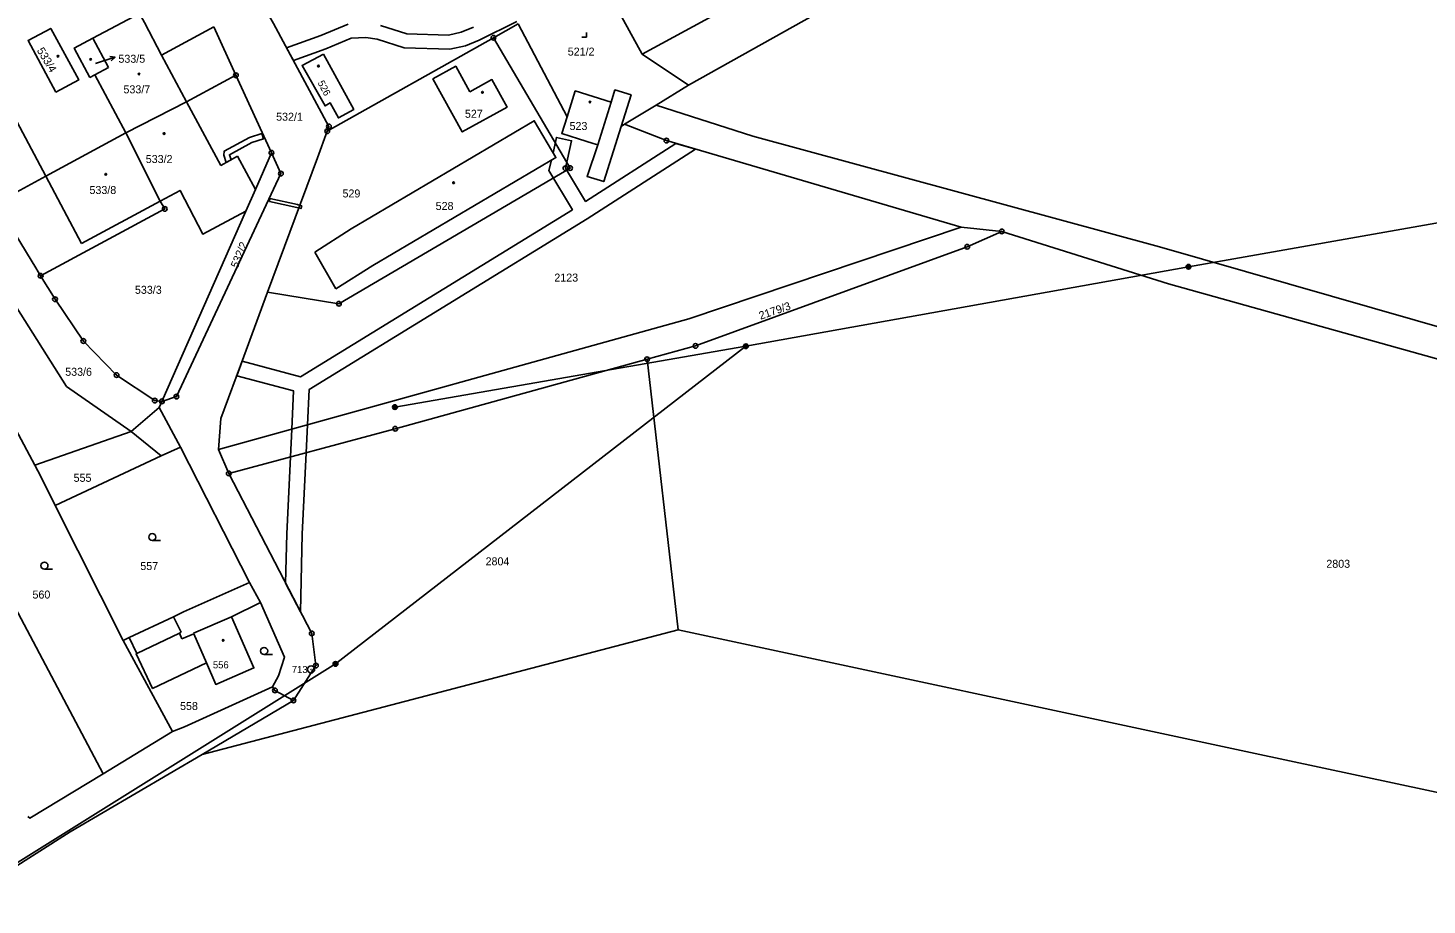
# Model space of a CAD drawing. Extents: x -504988 to -494607, y -1123820 to -1114018.
# Drawn here: x -497467 to -497169.8, y -1121271.7 to -1121085.3 of the extents above; entities that cross this region are included whole.
import ezdxf

# ---------------------------------------------------------------- set-up
doc = ezdxf.new("R2010")
doc.units = 0
for name, color, linetype in [('Hranice parcel', 7, 'Continuous'), ('Parcelní čísla', 7, 'Continuous'), ('Pop  PČ popisy', 7, 'Continuous'), ('Poz předměty', 7, 'Continuous'), ('Vnitřní kresba', 7, 'Continuous'), ('Věcná břemena k části', 7, 'Continuous'), ('Značky bodu BP', 7, 'Continuous'), ('Značky budov', 7, 'Continuous'), ('Značky kultur', 7, 'Continuous')]:
    doc.layers.add(name, color=color, linetype=linetype)

msp = doc.modelspace()

# ---------------------------------------------------------------- linework, layer by layer
at = {"layer": 'Hranice parcel'}
for p, q in [((-497326.68, -1121097.47), (-497278.36, -1121070.36)), ((-497368.15, -1121087.36), (-497362.92, -1121084.41)), ((-497352.5, -1121104.16), (-497362.92, -1121084.41)), ((-497449.93, -1121093.68), (-497453.25, -1121087.45)), ((-497422.86, -1121095.35), (-497427.56, -1121085.06)), ((-497368.15, -1121087.36), (-497403.47, -1121107.24)), ((-497336.51, -1121090.82), (-497326.68, -1121097.47)), ((-497452.84, -1121095.24), (-497449.93, -1121093.68)), ((-497452.84, -1121095.24), (-497453.88, -1121095.8)), ((-497446.25, -1121107.58), (-497452.84, -1121095.24)), ((-497415.33, -1121111.82), (-497422.86, -1121095.35)), ((-497326.68, -1121097.47), (-497333.59, -1121101.69)), ((-497333.59, -1121101.69), (-497340.26, -1121105.75)), ((-497313, -1121108.3), (-497333.59, -1121101.69)), ((-497340.26, -1121105.75), (-497341.01, -1121106.21)), ((-497446.25, -1121107.58), (-497438.94, -1121122.08)), ((-497415.33, -1121111.82), (-497413.31, -1121116.24)), ((-497413.31, -1121116.24), (-497435.51, -1121163.63)), ((-497438.59, -1121164.63), (-497420.76, -1121124.25)), ((-497268.76, -1121127.65), (-497260.14, -1121128.51)), ((-497260.14, -1121128.51), (-497224.71, -1121139.69)), ((-497406.12, -1121132.93), (-497401.6, -1121140.7)), ((-497464.35, -1121137.95), (-497461.3, -1121142.93)), ((-497416.12, -1121141.44), (-497400.97, -1121143.88)), ((-497335.5, -1121155.69), (-497328.91, -1121213.19)), ((-497475.5, -1121159.69), (-497465.57, -1121178.18)), ((-497440.12, -1121164.48), (-497438.59, -1121164.63)), ((-497435.51, -1121163.63), (-497438.59, -1121164.63)), ((-497491.31, -1121167.78), (-497451.07, -1121243.81)), ((-497465.57, -1121178.18), (-497445.11, -1121171.05)), ((-497438.77, -1121176.24), (-497445.11, -1121171.05)), ((-497461.25, -1121186.74), (-497438.77, -1121176.24)), ((-497426.55, -1121174.87), (-497424.38, -1121179.95)), ((-497461.25, -1121186.74), (-497446.83, -1121215.44)), ((-497417.63, -1121207.37), (-497419.94, -1121203.11)), ((-497446.83, -1121215.44), (-497436.32, -1121234.8)), ((-497430.04, -1121239.64), (-497328.91, -1121213.19)), ((-497410.63, -1121228.18), (-497430.04, -1121239.64)), ((-497451.07, -1121243.81), (-497436.32, -1121234.8))]:
    msp.add_line(p, q, dxfattribs=at)
for points in [[(-497301.42, -1121054.09), (-497344.04, -1121077.09), (-497336.51, -1121090.82)], [(-497336.51, -1121090.82), (-497294.14, -1121067.73), (-497301.42, -1121054.09)], [(-497430.47, -1121056.97), (-497414.87, -1121084.34), (-497403.09, -1121106.22), (-497403.47, -1121107.24)], [(-497453.25, -1121087.45), (-497443.38, -1121082.18), (-497442.32, -1121084.16), (-497438.65, -1121091.04), (-497427.56, -1121085.06)], [(-497461.11, -1121098.93), (-497467.03, -1121087.95), (-497462.2, -1121085.37), (-497456.27, -1121096.31), (-497461.11, -1121098.93)], [(-497453.88, -1121095.8), (-497457.2, -1121089.56), (-497453.25, -1121087.45)], [(-497400.97, -1121143.88), (-497351.84, -1121115.06), (-497368.15, -1121087.36)], [(-497404.26, -1121090.86), (-497408.79, -1121093.24), (-497403.93, -1121101.85), (-497402.81, -1121101.23), (-497401.09, -1121104.39), (-497397.82, -1121102.6), (-497404.26, -1121090.86)], [(-497373.16, -1121098.84), (-497376.16, -1121093.42), (-497381.01, -1121096.1), (-497374.75, -1121107.38), (-497365.23, -1121102.09), (-497368.48, -1121096.24), (-497373.16, -1121098.84)], [(-497422.86, -1121095.35), (-497433.33, -1121100.99), (-497446.25, -1121107.58)], [(-497341.01, -1121106.21), (-497338.9, -1121099.52), (-497342.32, -1121098.46), (-497343.12, -1121101.07), (-497350.77, -1121098.65), (-497352.5, -1121104.16)], [(-497401.6, -1121140.7), (-497393.74, -1121135.76), (-497354.86, -1121112.82), (-497359.47, -1121105.01), (-497398.35, -1121127.95), (-497406.12, -1121132.93)], [(-497352.5, -1121104.16), (-497353.63, -1121107.73), (-497350.03, -1121108.85), (-497346.92, -1121109.81), (-497345.99, -1121110.1), (-497348.24, -1121116.84), (-497344.7, -1121117.92), (-497341.01, -1121106.21)], [(-497340.26, -1121105.75), (-497331.39, -1121109.22), (-497268.76, -1121127.65)], [(-497473.48, -1121122.3), (-497463.27, -1121116.77), (-497446.25, -1121107.58)], [(-497403.47, -1121107.24), (-497405.55, -1121112.87), (-497416.12, -1121141.44)], [(-497024.32, -1121160.03), (-497054.02, -1121181.31), (-497226.59, -1121131.82), (-497313, -1121108.3)], [(-497420.76, -1121124.25), (-497418.73, -1121119.61), (-497415.33, -1121111.82)], [(-497438.94, -1121122.08), (-497434.74, -1121119.82), (-497429.9, -1121129.07), (-497420.76, -1121124.25)], [(-497438.94, -1121122.08), (-497437.98, -1121123.74), (-497464.35, -1121137.95)], [(-497464.35, -1121137.95), (-497465.39, -1121136.25), (-497469.57, -1121129.41), (-497471.07, -1121130.21)], [(-497426.55, -1121174.87), (-497326.59, -1121147.07), (-497268.76, -1121127.65)], [(-497260.14, -1121128.51), (-497267.46, -1121131.78), (-497325.19, -1121152.84), (-497335.5, -1121155.69)], [(-497416.12, -1121141.44), (-497421.17, -1121155.08), (-497426.05, -1121168.26), (-497426.55, -1121174.87)], [(-497224.71, -1121139.69), (-497106.85, -1121172.59), (-497052.82, -1121187.14)], [(-497445.11, -1121171.05), (-497458.87, -1121161.47), (-497470.26, -1121143.39)], [(-497461.3, -1121142.93), (-497455.28, -1121151.81), (-497448.21, -1121159.05), (-497440.12, -1121164.48)], [(-497335.5, -1121155.69), (-497388.99, -1121170.45), (-497424.38, -1121179.95)], [(-497445.11, -1121171.05), (-497439.17, -1121165.94), (-497438.59, -1121164.63)], [(-497419.94, -1121203.11), (-497434.67, -1121174.36), (-497438.77, -1121176.24)], [(-497465.57, -1121178.18), (-497464.28, -1121180.58), (-497461.25, -1121186.74)], [(-497424.38, -1121179.95), (-497406.76, -1121213.95), (-497405.85, -1121220.79), (-497410.63, -1121228.18)], [(-497419.94, -1121203.11), (-497434.03, -1121209.39), (-497436.14, -1121210.39), (-497445.51, -1121214.83)], [(-497445.51, -1121214.83), (-497443.92, -1121218.19), (-497444.06, -1121218.25), (-497440.58, -1121225.64), (-497429.12, -1121220.19), (-497427.13, -1121224.77), (-497419.05, -1121221.26), (-497423.78, -1121210.39), (-497417.63, -1121207.37)], [(-497415.06, -1121225.27), (-497413.8, -1121222.94), (-497412.57, -1121219.01), (-497417.63, -1121207.37)], [(-497446.83, -1121215.44), (-497446.38, -1121215.24), (-497445.51, -1121214.83)], [(-497328.91, -1121213.19), (-497207.25, -1121239.23), (-497085.58, -1121265.26), (-497027.04, -1121239.69)], [(-497436.32, -1121234.8), (-497433.81, -1121233.81), (-497415.06, -1121225.27)], [(-497410.63, -1121228.18), (-497414.57, -1121226.05), (-497415.06, -1121225.27)], [(-497430.04, -1121239.64), (-497458.1, -1121256.14), (-497610.28, -1121353.06), (-497671.16, -1121391.21)], [(-497467.06, -1121252.84), (-497466.67, -1121253.17), (-497451.07, -1121243.81)]]:
    msp.add_lwpolyline(points, dxfattribs=at)
at = {"layer": 'Pop  PČ popisy'}
for p, q in [((-497452.73, -1121092.81), (-497451.4, -1121092.39)), ((-497451.4, -1121092.39), (-497448.53, -1121091.51)), ((-497448.53, -1121091.51), (-497449.63, -1121091.33)), ((-497448.53, -1121091.51), (-497449.34, -1121092.28))]:
    msp.add_line(p, q, dxfattribs=at)
at = {"layer": 'Poz předměty'}
for p, q in [((-497025.16, -1121101.65), (-497220.45, -1121136.04)), ((-497220.45, -1121136.04), (-497314.49, -1121152.92)), ((-497314.49, -1121152.92), (-497401.7, -1121220.43)), ((-497314.49, -1121152.92), (-497389.09, -1121165.86)), ((-497401.7, -1121220.43), (-497478.06, -1121268.08))]:
    msp.add_line(p, q, dxfattribs=at)
for centre, radius in [((-497220.45, -1121136.04), 0.5), ((-497220.45, -1121136.04), 0.4), ((-497220.45, -1121136.04), 0.3), ((-497220.45, -1121136.04), 0.2), ((-497220.45, -1121136.04), 0.1), ((-497314.49, -1121152.92), 0.5), ((-497314.49, -1121152.92), 0.4), ((-497314.49, -1121152.92), 0.3), ((-497314.49, -1121152.92), 0.2), ((-497314.49, -1121152.92), 0.1), ((-497389.09, -1121165.86), 0.5), ((-497389.09, -1121165.86), 0.4), ((-497389.09, -1121165.86), 0.3), ((-497389.09, -1121165.86), 0.2), ((-497389.09, -1121165.86), 0.1), ((-497401.7, -1121220.43), 0.5), ((-497401.7, -1121220.43), 0.4), ((-497401.7, -1121220.43), 0.3), ((-497401.7, -1121220.43), 0.2), ((-497401.7, -1121220.43), 0.1)]:
    msp.add_circle(centre, radius, dxfattribs=at)
at = {"layer": 'Vnitřní kresba'}
for p, q in [((-497433.33, -1121100.99), (-497438.65, -1121091.04)), ((-497463.27, -1121116.77), (-497473.72, -1121097.12)), ((-497426.09, -1121114.54), (-497433.33, -1121100.99)), ((-497345.99, -1121110.1), (-497343.12, -1121101.07)), ((-497426.09, -1121114.54), (-497422.5, -1121112.52)), ((-497422.5, -1121112.52), (-497418.73, -1121119.61)), ((-497463.27, -1121116.77), (-497459.42, -1121124.02)), ((-497438.94, -1121122.08), (-497455.66, -1121131.08)), ((-497455.66, -1121131.08), (-497459.42, -1121124.02)), ((-497439.17, -1121165.94), (-497434.67, -1121174.36)), ((-497436.14, -1121210.39), (-497434.48, -1121213.69)), ((-497431.85, -1121213.91), (-497423.78, -1121210.39)), ((-497443.92, -1121218.19), (-497434.87, -1121213.86)), ((-497434.48, -1121213.69), (-497434.87, -1121213.86)), ((-497434.87, -1121213.86), (-497434.32, -1121215.13)), ((-497434.32, -1121215.13), (-497431.79, -1121214.02)), ((-497431.79, -1121214.02), (-497431.85, -1121213.91)), ((-497431.79, -1121214.02), (-497429.12, -1121220.19))]:
    msp.add_line(p, q, dxfattribs=at)
at = {"layer": 'Věcná břemena k části'}
for points in [[(-497399.03, -1121084.51), (-497404.85, -1121086.89), (-497412.08, -1121089.52), (-497410.64, -1121092.19), (-497403.77, -1121089.69), (-497398.35, -1121087.47), (-497395.22, -1121087.3), (-497392.86, -1121087.67), (-497387.09, -1121089.53), (-497377.42, -1121089.81), (-497374.11, -1121089.09), (-497371.16, -1121087.89), (-497363.2, -1121083.88)], [(-497372.4, -1121085.15), (-497375.01, -1121086.21), (-497377.7, -1121086.81), (-497386.57, -1121086.55), (-497392.16, -1121084.75)]]:
    msp.add_lwpolyline(points, dxfattribs=at)
for points in [[(-497424.95, -1121113.9), (-497423.88, -1121113.3), (-497424.23, -1121112.22), (-497419.51, -1121109.64), (-497417.03, -1121108.87), (-497417.38, -1121107.72), (-497419.99, -1121108.54), (-497425.33, -1121111.46), (-497425.45, -1121112.32)], [(-497325.17, -1121111.05), (-497329.36, -1121109.82), (-497348.57, -1121122.15), (-497352.83, -1121115.11), (-497352.39, -1121113.14), (-497351.53, -1121109.26), (-497354.75, -1121108.55), (-497355.47, -1121111.79), (-497354.86, -1121112.82), (-497355.83, -1121113.39), (-497356.39, -1121115.59), (-497351.36, -1121123.91), (-497409.15, -1121159.39), (-497421.55, -1121156.09), (-497422.7, -1121159.2), (-497410.6, -1121162.41), (-497411, -1121170.54), (-497411.28, -1121176.43), (-497412.07, -1121192.75), (-497412.3, -1121203.27), (-497409.13, -1121209.39), (-497408.77, -1121192.86), (-497407.94, -1121175.54), (-497407.65, -1121169.61), (-497407.29, -1121162.11), (-497348.22, -1121125.86)], [(-497415.75, -1121122.15), (-497409.95, -1121123.41), (-497409.5, -1121123.54), (-497409.29, -1121122.98), (-497409.8, -1121122.83), (-497415.62, -1121121.56)], [(-497409.29, -1121122.98), (-497409.5, -1121123.54), (-497409.03, -1121123.68), (-497408.86, -1121123.1)]]:
    msp.add_lwpolyline(points, close=True, dxfattribs=at)
at = {"layer": 'Značky bodu BP'}
for centre, radius in [((-497368.15, -1121087.36), 0.5), ((-497368.15, -1121087.36), 0.0303), ((-497422.86, -1121095.35), 0.5), ((-497422.86, -1121095.35), 0.0303), ((-497403.09, -1121106.22), 0.5), ((-497403.47, -1121107.24), 0.5), ((-497403.47, -1121107.24), 0.0303), ((-497403.09, -1121106.22), 0.0303), ((-497331.39, -1121109.22), 0.5), ((-497415.33, -1121111.82), 0.5), ((-497331.39, -1121109.22), 0.0303), ((-497415.33, -1121111.82), 0.0303), ((-497352.83, -1121115.11), 0.5), ((-497351.84, -1121115.06), 0.5), ((-497413.31, -1121116.24), 0.5), ((-497413.31, -1121116.24), 0.0303), ((-497352.83, -1121115.11), 0.0303), ((-497351.84, -1121115.06), 0.0303), ((-497437.98, -1121123.74), 0.5), ((-497437.98, -1121123.74), 0.0303), ((-497260.14, -1121128.51), 0.5), ((-497260.14, -1121128.51), 0.0303), ((-497267.46, -1121131.78), 0.5), ((-497267.46, -1121131.78), 0.0303), ((-497464.35, -1121137.95), 0.5), ((-497464.35, -1121137.95), 0.0303), ((-497461.3, -1121142.93), 0.5), ((-497461.3, -1121142.93), 0.0303), ((-497400.97, -1121143.88), 0.5), ((-497400.97, -1121143.88), 0.0303), ((-497455.28, -1121151.81), 0.5), ((-497455.28, -1121151.81), 0.0303), ((-497325.19, -1121152.84), 0.5), ((-497325.19, -1121152.84), 0.0303), ((-497335.5, -1121155.69), 0.5), ((-497335.5, -1121155.69), 0.0303), ((-497448.21, -1121159.05), 0.5), ((-497448.21, -1121159.05), 0.0303), ((-497440.12, -1121164.48), 0.5), ((-497440.12, -1121164.48), 0.0303), ((-497438.59, -1121164.63), 0.5), ((-497438.59, -1121164.63), 0.0303), ((-497435.51, -1121163.63), 0.5), ((-497435.51, -1121163.63), 0.0303), ((-497388.99, -1121170.45), 0.5), ((-497388.99, -1121170.45), 0.0303), ((-497424.38, -1121179.95), 0.5), ((-497424.38, -1121179.95), 0.0303), ((-497406.76, -1121213.95), 0.5), ((-497406.76, -1121213.95), 0.0303), ((-497406.88, -1121221.61), 0.75), ((-497406.88, -1121221.61), 0.03), ((-497405.85, -1121220.79), 0.5), ((-497405.85, -1121220.79), 0.0303), ((-497414.57, -1121226.05), 0.5), ((-497414.57, -1121226.05), 0.0303), ((-497410.63, -1121228.18), 0.5), ((-497410.63, -1121228.18), 0.0303)]:
    msp.add_circle(centre, radius, dxfattribs=at)
at = {"layer": 'Značky budov'}
for centre in [(-497460.65, -1121091.29), (-497453.73, -1121091.96), (-497405.32, -1121093.4), (-497443.47, -1121095.08), (-497370.48, -1121098.96), (-497347.62, -1121101.02), (-497438.11, -1121107.73), (-497450.51, -1121116.38), (-497376.61, -1121118.18), (-497425.57, -1121215.42)]:
    msp.add_circle(centre, 0.175, dxfattribs=at)
at = {"layer": 'Značky kultur'}
for p, q in [((-497349.37, -1121087.22), (-497348.37, -1121087.22)), ((-497348.37, -1121087.22), (-497348.37, -1121086.22)), ((-497440.63, -1121194.22), (-497438.88, -1121194.22)), ((-497463.55, -1121200.29), (-497461.8, -1121200.29)), ((-497416.86, -1121218.43), (-497415.11, -1121218.43))]:
    msp.add_line(p, q, dxfattribs=at)
for centre in [(-497440.63, -1121193.47), (-497463.55, -1121199.54), (-497416.86, -1121217.68)]:
    msp.add_circle(centre, 0.75, dxfattribs=at)

# ---------------------------------------------------------------- texts
at = {"layer": 'Parcelní čísla'}
for s, height, rotation, p in [('533/4', 1.7, 301, (-497465.23, -1121090.05)), ('526', 1.5, 298, (-497405.55, -1121096.93)), ('532/2', 1.7, 68, (-497422.47, -1121136.45)), ('2179/3', 1.7, 19, (-497311.39, -1121147.3))]:
    msp.add_text(s, height=height, rotation=rotation, dxfattribs=at).set_placement(p)
for s, height, p in [('533/5', 1.7, (-497447.83, -1121092.68)), ('521/2', 1.7, (-497352.35, -1121091.16)), ('533/7', 1.7, (-497446.76, -1121099.18)), ('527', 1.7, (-497374.2, -1121104.37)), ('532/1', 1.7, (-497414.32, -1121105)), ('523', 1.7, (-497351.97, -1121106.97)), ('533/2', 1.7, (-497442.02, -1121113.99)), ('533/8', 1.7, (-497453.98, -1121120.57)), ('529', 1.7, (-497400.21, -1121121.3)), ('528', 1.7, (-497380.42, -1121123.96)), ('2123', 1.7, (-497355.2, -1121139.18)), ('533/3', 1.7, (-497444.32, -1121141.78)), ('533/6', 1.7, (-497459.14, -1121159.2)), ('555', 1.7, (-497457.35, -1121181.73)), ('2804', 1.7, (-497369.81, -1121199.48)), ('557', 1.7, (-497443.17, -1121200.47)), ('2803', 1.7, (-497191.16, -1121200)), ('560', 1.7, (-497466.09, -1121206.54)), ('556', 1.5, (-497427.75, -1121221.37)), ('558', 1.7, (-497434.73, -1121230.22))]:
    msp.add_text(s, height=height, dxfattribs=at).set_placement(p)
at = {"layer": 'Značky bodu BP'}
msp.add_text('713', height=1.5, dxfattribs=at).set_placement((-497410.98, -1121222.36))

doc.saveas('drawing.dxf')
